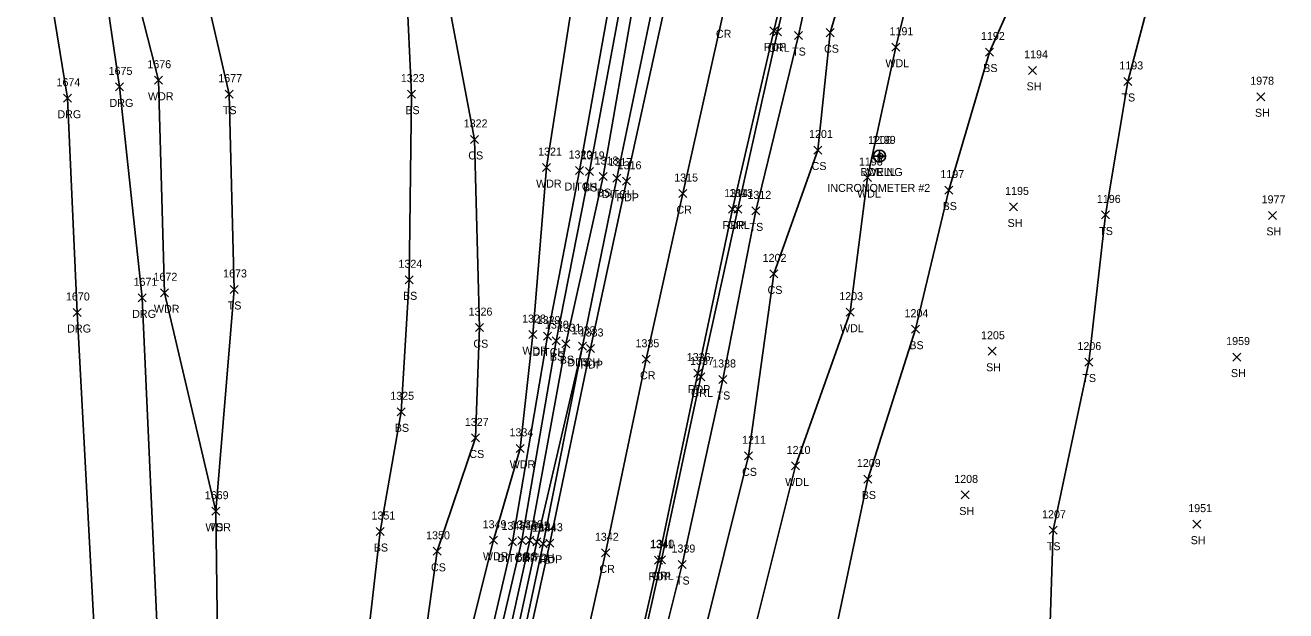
# Model space of a CAD drawing. Extents: x 1551995 to 1555700, y 777276 to 783130.
# Drawn here: x 1554731.6 to 1555046.7, y 777809.8 to 777956 of the extents above; entities that cross this region are included whole.
import ezdxf

# ---------------------------------------------------------------- set-up
doc = ezdxf.new("R2010")
doc.units = 0
for name, color, linetype in [('D_A', 7, 'Continuous'), ('D_I', 7, 'Continuous'), ('D_TIC', 7, 'Continuous'), ('DD', 7, 'Continuous'), ('G_A', 7, 'Continuous'), ('G_I', 7, 'Continuous'), ('GA_P', 7, 'Continuous'), ('L_A', 7, 'Continuous'), ('L_I', 7, 'Continuous'), ('L_TIC', 7, 'Continuous'), ('LAWA', 7, 'Continuous'), ('LELB', 7, 'Continuous'), ('P_A', 7, 'Continuous'), ('P_I', 7, 'Continuous'), ('P_TIC', 7, 'Continuous'), ('PET', 7, 'Continuous'), ('PRC', 7, 'Continuous'), ('R_A', 7, 'Continuous'), ('R_I', 7, 'Continuous'), ('R_TIC', 7, 'Continuous'), ('RDG', 7, 'Continuous'), ('RGR', 7, 'Continuous'), ('U_A', 7, 'Continuous'), ('U_C', 7, 'Continuous'), ('U_I', 7, 'Continuous'), ('UWW', 7, 'Continuous')]:
    doc.layers.add(name, color=color, linetype=linetype)

msp = doc.modelspace()

# ---------------------------------------------------------------- linework, layer by layer
at = {"layer": 'D_TIC'}
for points in [[(1554869.22, 777918.72), (1554871.22, 777920.72)], [(1554871.22, 777918.72), (1554869.22, 777920.72)], [(1554878.52, 777916.82), (1554880.52, 777918.82)], [(1554880.52, 777916.82), (1554878.52, 777918.82)], [(1554861.18, 777877.39), (1554863.18, 777879.39)], [(1554863.18, 777877.39), (1554861.18, 777879.39)], [(1554869.92, 777874.83), (1554871.92, 777876.83)], [(1554871.92, 777874.83), (1554869.92, 777876.83)], [(1554852.39, 777825.98), (1554854.39, 777827.98)], [(1554854.39, 777825.98), (1554852.39, 777827.98)], [(1554858.53, 777826.03), (1554860.53, 777828.03)], [(1554860.53, 777826.03), (1554858.53, 777828.03)]]:
    msp.add_lwpolyline(points, dxfattribs=at)
at = {"layer": 'DD'}
for points in [[(1554922.06, 778109.96), (1554923.19, 778109.15), (1554925.69, 778108.05), (1554928.67, 778106.77), (1554922.03, 778089.94), (1554922.01, 778087.44), (1554918.96, 778075.67), (1554907.32, 778037.79), (1554897.01, 777996.11), (1554888.71, 777961.75), (1554879.52, 777917.82), (1554870.92, 777875.83), (1554859.53, 777827.03), (1554848.28, 777775.3), (1554842.42, 777742.65), (1554832.08, 777696.16), (1554826.68, 777674.46), (1554825.9, 777662.94)], [(1554922.06, 778109.96), (1554914.41, 778091.96), (1554910.4, 778079.82), (1554897.71, 778040.99), (1554886.57, 777998.5), (1554878.33, 777965.3), (1554870.22, 777919.72), (1554862.18, 777878.39), (1554853.39, 777826.98), (1554841.81, 777777.5)]]:
    msp.add_lwpolyline(points, dxfattribs=at)
at = {"layer": 'GA_P'}
for p, q in [((1554945.18, 777923.34), (1554945.18, 777924.84)), ((1554945.18, 777923.34), (1554943.68, 777923.34)), ((1554946.68, 777923.34), (1554945.18, 777923.34)), ((1554945.18, 777921.84), (1554945.18, 777923.34))]:
    msp.add_line(p, q, dxfattribs=at)
for start, end in [(90, 180), (0, 90), (180, 270), (270, 0)]:
    msp.add_arc((1554945.18, 777923.34), 1.5, start, end, dxfattribs=at)
at = {"layer": 'L_TIC'}
for points in [[(1554923.92, 777952.42), (1554925.92, 777954.42)], [(1554925.92, 777952.42), (1554923.92, 777954.42)], [(1554931.87, 777953.14), (1554933.87, 777955.14)], [(1554933.87, 777953.14), (1554931.87, 777955.14)], [(1554948.24, 777949.5), (1554950.24, 777951.5)], [(1554950.24, 777949.5), (1554948.24, 777951.5)], [(1554971.66, 777948.31), (1554973.66, 777950.31)], [(1554973.66, 777948.31), (1554971.66, 777950.31)], [(1554763.95, 777941.26), (1554765.95, 777943.26)], [(1554765.95, 777941.26), (1554763.95, 777943.26)], [(1554982.45, 777943.73), (1554984.45, 777945.73)], [(1554984.45, 777943.73), (1554982.45, 777945.73)], [(1555006.25, 777940.96), (1555008.25, 777942.96)], [(1555008.25, 777940.96), (1555006.25, 777942.96)], [(1554781.62, 777937.78), (1554783.62, 777939.78)], [(1554783.62, 777937.78), (1554781.62, 777939.78)], [(1554827.21, 777937.79), (1554829.21, 777939.79)], [(1554829.21, 777937.79), (1554827.21, 777939.79)], [(1555039.54, 777937.14), (1555041.54, 777939.14)], [(1555041.54, 777937.14), (1555039.54, 777939.14)], [(1554842.93, 777926.48), (1554844.93, 777928.48)], [(1554844.93, 777926.48), (1554842.93, 777928.48)], [(1554928.76, 777923.84), (1554930.76, 777925.84)], [(1554930.76, 777923.84), (1554928.76, 777925.84)], [(1554860.96, 777919.45), (1554862.96, 777921.45)], [(1554862.96, 777919.45), (1554860.96, 777921.45)], [(1554871.66, 777918.49), (1554873.66, 777920.49)], [(1554873.66, 777918.49), (1554871.66, 777920.49)], [(1554875.08, 777917.21), (1554877.08, 777919.21)], [(1554877.08, 777917.21), (1554875.08, 777919.21)], [(1554941.15, 777916.97), (1554943.15, 777918.97)], [(1554943.15, 777916.97), (1554941.15, 777918.97)], [(1554961.52, 777913.84), (1554963.52, 777915.84)], [(1554963.52, 777913.84), (1554961.52, 777915.84)], [(1554977.71, 777909.63), (1554979.71, 777911.63)], [(1554979.71, 777909.63), (1554977.71, 777911.63)], [(1554913.28, 777908.64), (1554915.28, 777910.64)], [(1554915.28, 777908.64), (1554913.28, 777910.64)], [(1555000.69, 777907.63), (1555002.69, 777909.63)], [(1555002.69, 777907.63), (1555000.69, 777909.63)], [(1555042.39, 777907.52), (1555044.39, 777909.52)], [(1555044.39, 777907.52), (1555042.39, 777909.52)], [(1554826.61, 777891.43), (1554828.61, 777893.43)], [(1554828.61, 777891.43), (1554826.61, 777893.43)], [(1554917.75, 777892.91), (1554919.75, 777894.91)], [(1554919.75, 777892.91), (1554917.75, 777894.91)], [(1554765.43, 777888.19), (1554767.43, 777890.19)], [(1554767.43, 777888.19), (1554765.43, 777890.19)], [(1554782.83, 777889.02), (1554784.83, 777891.02)], [(1554784.83, 777889.02), (1554782.83, 777891.02)], [(1554936.88, 777883.35), (1554938.88, 777885.35)], [(1554938.88, 777883.35), (1554936.88, 777885.35)], [(1554844.21, 777879.49), (1554846.21, 777881.49)], [(1554846.21, 777879.49), (1554844.21, 777881.49)], [(1554953.2, 777879.1), (1554955.2, 777881.1)], [(1554955.2, 777879.1), (1554953.2, 777881.1)], [(1554857.53, 777877.75), (1554859.53, 777879.75)], [(1554859.53, 777877.75), (1554857.53, 777879.75)], [(1554863.33, 777876.23), (1554865.33, 777878.23)], [(1554865.33, 777876.23), (1554863.33, 777878.23)], [(1554865.8, 777875.47), (1554867.8, 777877.47)], [(1554867.8, 777875.47), (1554865.8, 777877.47)], [(1554869.92, 777874.83), (1554871.92, 777876.83)], [(1554871.92, 777874.83), (1554869.92, 777876.83)], [(1554972.33, 777873.59), (1554974.33, 777875.59)], [(1554974.33, 777873.59), (1554972.33, 777875.59)], [(1555033.54, 777872.14), (1555035.54, 777874.14)], [(1555035.54, 777872.14), (1555033.54, 777874.14)], [(1554996.48, 777870.9), (1554998.48, 777872.9)], [(1554998.48, 777870.9), (1554996.48, 777872.9)], [(1554905.04, 777866.54), (1554907.04, 777868.54)], [(1554907.04, 777866.54), (1554905.04, 777868.54)], [(1554824.56, 777858.47), (1554826.56, 777860.47)], [(1554826.56, 777858.47), (1554824.56, 777860.47)], [(1554843.2, 777851.94), (1554845.2, 777853.94)], [(1554845.2, 777851.94), (1554843.2, 777853.94)], [(1554854.37, 777849.35), (1554856.37, 777851.35)], [(1554856.37, 777849.35), (1554854.37, 777851.35)], [(1554911.39, 777847.48), (1554913.39, 777849.48)], [(1554913.39, 777847.48), (1554911.39, 777849.48)], [(1554923.17, 777844.95), (1554925.17, 777846.95)], [(1554925.17, 777844.95), (1554923.17, 777846.95)], [(1554941.29, 777841.69), (1554943.29, 777843.69)], [(1554943.29, 777841.69), (1554941.29, 777843.69)], [(1554965.63, 777837.71), (1554967.63, 777839.71)], [(1554967.63, 777837.71), (1554965.63, 777839.71)], [(1554778.3, 777833.65), (1554780.3, 777835.65)], [(1554780.3, 777833.65), (1554778.3, 777835.65)], [(1554778.3, 777833.65), (1554780.3, 777835.65)], [(1554780.3, 777833.65), (1554778.3, 777835.65)], [(1554819.31, 777828.58), (1554821.31, 777830.58)], [(1554821.31, 777828.58), (1554819.31, 777830.58)], [(1554987.59, 777828.9), (1554989.59, 777830.9)], [(1554989.59, 777828.9), (1554987.59, 777830.9)], [(1555023.47, 777830.42), (1555025.47, 777832.42)], [(1555025.47, 777830.42), (1555023.47, 777832.42)], [(1554847.67, 777826.4), (1554849.67, 777828.4)], [(1554849.67, 777826.4), (1554847.67, 777828.4)], [(1554854.73, 777826.33), (1554856.73, 777828.33)], [(1554856.73, 777826.33), (1554854.73, 777828.33)], [(1554856.76, 777826.38), (1554858.76, 777828.38)], [(1554858.76, 777826.38), (1554856.76, 777828.38)], [(1554860.08, 777825.54), (1554862.08, 777827.54)], [(1554862.08, 777825.54), (1554860.08, 777827.54)], [(1554833.62, 777823.64), (1554835.62, 777825.64)], [(1554835.62, 777823.64), (1554833.62, 777825.64)], [(1554894.88, 777820.34), (1554896.88, 777822.34)], [(1554896.88, 777820.34), (1554894.88, 777822.34)]]:
    msp.add_lwpolyline(points, dxfattribs=at)
at = {"layer": 'LAWA'}
for points in [[(1555000.96, 778294.87), (1554977.33, 778249.83), (1554953.65, 778203.43), (1554934.13, 778158.37), (1554921.74, 778129.69), (1554915, 778109.12), (1554905.48, 778082.18), (1554899.62, 778064.01), (1554889.87, 778042.09), (1554882.71, 778000.01), (1554871.69, 777971.47), (1554868.37, 777961.54), (1554861.96, 777920.45), (1554858.53, 777878.75), (1554855.37, 777850.35), (1554848.67, 777827.4), (1554836.72, 777779.63)], [(1555085.12, 778246.6), (1555062.11, 778217.51), (1555036.75, 778197.89), (1555030.02, 778178.79), (1555023.09, 778154.13), (1555005.22, 778133.85), (1555000.72, 778121.06), (1554983.85, 778091.44), (1554975.19, 778092.03), (1554970.99, 778074.93), (1554967.22, 778059.88), (1554967.17, 778023.98), (1554956.28, 777979.25), (1554949.24, 777950.5), (1554942.15, 777917.97), (1554937.88, 777884.35), (1554924.17, 777845.95), (1554911.99, 777797.39)], [(1554753.38, 777699.82), (1554782.17, 777718.85), (1554781.09, 777755.32), (1554779.76, 777796.52), (1554779.3, 777834.65), (1554766.43, 777889.19), (1554764.95, 777942.26), (1554753, 777988.87), (1554759.44, 778026.67), (1554773.64, 778068.32), (1554781.91, 778071.15), (1554798.07, 778075.08), (1554813.64, 778080.72)]]:
    msp.add_lwpolyline(points, dxfattribs=at)
at = {"layer": 'LELB'}
for points in [[(1555012.41, 778287.51), (1554987.42, 778242.35), (1554964.94, 778198.34), (1554949.46, 778165.73), (1554942.04, 778145.43), (1554936.48, 778136), (1554931.2, 778126.36), (1554925.41, 778115.96), (1554925.69, 778108.05), (1554919.03, 778090.31), (1554918.44, 778089.95), (1554914.24, 778077.2), (1554901.57, 778039.07), (1554894.39, 777997.12), (1554883.88, 777962.74), (1554876.08, 777918.21), (1554866.8, 777876.47), (1554857.76, 777827.38), (1554846.36, 777775.83)], [(1554779.3, 777834.65), (1554783.83, 777890.02), (1554782.62, 777938.78), (1554771.14, 777988.74), (1554776.92, 778021.99), (1554786.75, 778049.64), (1554798.07, 778075.08), (1554788.09, 778101.73), (1554789.42, 778116.55), (1554786.7, 778124.19), (1554777.52, 778125.41), (1554776.84, 778134.51)], [(1554925.41, 778115.96), (1554923.19, 778109.15), (1554916.16, 778091.42), (1554916.06, 778090.22), (1554912.35, 778078.2), (1554899.83, 778040.36), (1554892.76, 777999.54), (1554881.05, 777964.27), (1554872.66, 777919.49), (1554864.33, 777877.23), (1554855.73, 777827.33), (1554843.83, 777776.52)], [(1554956.78, 778082.85), (1554952.54, 778067.25), (1554941.7, 778025.45), (1554932.23, 777987.42), (1554924.92, 777953.42), (1554914.28, 777909.64), (1554906.04, 777867.54), (1554895.88, 777821.34), (1554882.23, 777767.05), (1554874.85, 777730.37), (1554865.16, 777689.06), (1554854.06, 777643.96), (1554841.07, 777598.56), (1554825.8, 777560.58)], [(1554954.84, 778026.93), (1554940.94, 777981.64), (1554932.87, 777954.14), (1554929.76, 777924.84), (1554918.75, 777893.91), (1554912.39, 777848.48), (1554900.26, 777799.7), (1554891.71, 777757.62), (1554881.43, 777720.27), (1554874.58, 777680.06), (1554873.83, 777672.65), (1554864.12, 777644.24), (1554854.56, 777607.14), (1554832.26, 777556.58)], [(1555000.87, 778001.08), (1555009.49, 778000.82), (1555019.32, 777999.5), (1555016.45, 777976.79), (1555007.25, 777941.96), (1555001.69, 777908.63), (1554997.48, 777871.9), (1554988.59, 777829.9), (1554987.68, 777801.59), (1554990.67, 777771.72), (1554987.39, 777735.48), (1554982.18, 777719.34), (1554965.91, 777692.12), (1554960.8, 777672.01)], [(1554989.73, 777998.18), (1554984.34, 777975.58), (1554972.66, 777949.31), (1554962.52, 777914.84), (1554954.2, 777880.1), (1554942.29, 777842.69), (1554932.5, 777796.7), (1554925.54, 777781.17), (1554929.46, 777763.36)], [(1554818.74, 777989.99), (1554826.95, 777965.67), (1554828.21, 777938.79), (1554827.61, 777892.43), (1554825.56, 777859.47), (1554820.31, 777829.58), (1554817.04, 777800.55), (1554813.37, 777784.98), (1554810.59, 777751.68), (1554805.09, 777735), (1554803.57, 777724.87), (1554801.62, 777701.82), (1554799.08, 777679.52), (1554798, 777658.89), (1554794.95, 777639.81), (1554778.13, 777607.5), (1554759.36, 777559.57), (1554752.31, 777545.79)], [(1554828.62, 777989.99), (1554839.45, 777979.91), (1554836.31, 777967.58), (1554843.93, 777927.48), (1554845.21, 777880.49), (1554844.2, 777852.94), (1554834.62, 777824.64), (1554828.42, 777780.47), (1554821.65, 777751.51), (1554810.59, 777751.68)], [(1554870.92, 777875.83), (1554861.08, 777826.54), (1554850.05, 777774.56), (1554843.76, 777742.91), (1554832.54, 777696.52), (1554826.68, 777674.46)]]:
    msp.add_lwpolyline(points, dxfattribs=at)
at = {"layer": 'P_TIC'}
for points in [[(1554917.72, 777953.59), (1554919.72, 777955.59)], [(1554919.72, 777953.59), (1554917.72, 777955.59)], [(1554880.9, 777916.03), (1554882.9, 777918.03)], [(1554882.9, 777916.03), (1554880.9, 777918.03)], [(1554894.98, 777912.96), (1554896.98, 777914.96)], [(1554896.98, 777912.96), (1554894.98, 777914.96)], [(1554907.46, 777909.08), (1554909.46, 777911.08)], [(1554909.46, 777909.08), (1554907.46, 777911.08)], [(1554871.92, 777874.28), (1554873.92, 777876.28)], [(1554873.92, 777874.28), (1554871.92, 777876.28)], [(1554885.88, 777871.59), (1554887.88, 777873.59)], [(1554887.88, 777871.59), (1554885.88, 777873.59)], [(1554898.75, 777868.14), (1554900.75, 777870.14)], [(1554900.75, 777868.14), (1554898.75, 777870.14)], [(1554861.74, 777825.66), (1554863.74, 777827.66)], [(1554863.74, 777825.66), (1554861.74, 777827.66)], [(1554875.72, 777823.26), (1554877.72, 777825.26)], [(1554877.72, 777823.26), (1554875.72, 777825.26)], [(1554888.9, 777821.39), (1554890.9, 777823.39)], [(1554890.9, 777821.39), (1554888.9, 777823.39)]]:
    msp.add_lwpolyline(points, dxfattribs=at)
at = {"layer": 'PET'}
for points in [[(1555086.85, 778385.99), (1555058.53, 778347.95), (1555034.13, 778312.76), (1555016.69, 778284.76), (1554990.68, 778240.38), (1554968.05, 778196.33), (1554953.03, 778164.25), (1554940.37, 778132.83), (1554930.99, 778106.02), (1554923.77, 778083.63), (1554909.85, 778036.75), (1554900.04, 777995.37), (1554891.67, 777961.45), (1554881.9, 777917.03), (1554872.92, 777875.28), (1554862.74, 777826.66), (1554851.19, 777774.32)], [(1555108.52, 778369.81), (1555078.86, 778330.23), (1555056.92, 778298.28), (1555038.33, 778268.72), (1555013, 778223.52), (1554996, 778190.4), (1554978.91, 778154.53), (1554967.24, 778125.11), (1554957.25, 778096.67), (1554950.17, 778073.38), (1554937.06, 778028.22), (1554926.8, 777988.52), (1554918.72, 777954.59), (1554908.46, 777910.08), (1554899.75, 777869.14), (1554889.9, 777822.39), (1554877.4, 777767.74)]]:
    msp.add_lwpolyline(points, dxfattribs=at)
at = {"layer": 'PRC'}
msp.add_lwpolyline([(1555098.33, 778377.48), (1555069.71, 778339.49), (1555045.49, 778304.7), (1555028.73, 778278.05), (1555002.89, 778234.08), (1554980, 778189.5), (1554966.22, 778159.18), (1554954.38, 778129.46), (1554944.07, 778101.03), (1554941.59, 778092.54), (1554937.34, 778078.77), (1554924.27, 778032.77), (1554914.16, 777991.62), (1554905.84, 777957.86), (1554895.98, 777913.96), (1554886.88, 777872.59), (1554876.72, 777824.26), (1554864.6, 777770.35)], dxfattribs=at)
at = {"layer": 'R_TIC'}
for points in [[(1554918.66, 777953.37), (1554920.66, 777955.37)], [(1554920.66, 777953.37), (1554918.66, 777955.37)], [(1554754.21, 777939.6), (1554756.21, 777941.6)], [(1554756.21, 777939.6), (1554754.21, 777941.6)], [(1554741.18, 777936.77), (1554743.18, 777938.77)], [(1554743.18, 777936.77), (1554741.18, 777938.77)], [(1554908.72, 777909.11), (1554910.72, 777911.11)], [(1554910.72, 777909.11), (1554908.72, 777911.11)], [(1554759.87, 777886.93), (1554761.87, 777888.93)], [(1554761.87, 777886.93), (1554759.87, 777888.93)], [(1554743.63, 777883.27), (1554745.63, 777885.27)], [(1554745.63, 777883.27), (1554743.63, 777885.27)], [(1554899.5, 777867.18), (1554901.5, 777869.18)], [(1554901.5, 777867.18), (1554899.5, 777869.18)], [(1554889.69, 777821.54), (1554891.69, 777823.54)], [(1554891.69, 777821.54), (1554889.69, 777823.54)]]:
    msp.add_lwpolyline(points, dxfattribs=at)
at = {"layer": 'RDG'}
for points in [[(1554731.76, 777736.57), (1554744.54, 777760.39), (1554749.58, 777791.25), (1554744.63, 777884.27), (1554742.18, 777937.77), (1554733.78, 777989.36), (1554731.62, 778029.74), (1554732.87, 778072.64), (1554738.87, 778112.72), (1554741.1, 778122.89), (1554752.14, 778165.58), (1554757.04, 778182.47), (1554765.14, 778213.69), (1554774.89, 778246.18), (1554785.77, 778269.3), (1554800.7, 778290.2), (1554833.81, 778326.22), (1554863.94, 778353.44), (1554894.55, 778381.82), (1554916.32, 778408.8)], [(1554765.41, 777786.83), (1554760.87, 777887.93), (1554755.21, 777940.6), (1554748.12, 777988.97), (1554746.63, 778028.6), (1554748.07, 778068.94), (1554755.05, 778099.35), (1554759.31, 778115.55), (1554764.29, 778135.87), (1554767.84, 778151.77), (1554770.94, 778162.89), (1554771.35, 778163.02), (1554773.41, 778171.97), (1554775.55, 778183.39), (1554780.94, 778209.88), (1554780.41, 778210.35), (1554788.23, 778232), (1554795.94, 778253.78), (1554801.81, 778267.78), (1554821.53, 778293.59), (1554841.19, 778314.82), (1554873.15, 778342.35), (1554907.49, 778367.57), (1554931.47, 778399.39)]]:
    msp.add_lwpolyline(points, dxfattribs=at)
at = {"layer": 'RGR'}
msp.add_lwpolyline([(1555039.56, 778268.3), (1555013.62, 778223), (1554996.63, 778189.88), (1554979.88, 778154.08), (1554968.24, 778124.65), (1554958.2, 778096.32), (1554950.97, 778072.94), (1554937.27, 778027.95), (1554927.65, 777988.1), (1554919.66, 777954.37), (1554909.72, 777910.11), (1554900.5, 777868.18), (1554890.69, 777822.54), (1554878.36, 777767.59), (1554870.52, 777731.32), (1554860.9, 777689.38), (1554849.55, 777645.14), (1554835.81, 777600.33), (1554822.79, 777564.15), (1554817.07, 777548.72), (1554816.7, 777536.06)], dxfattribs=at)
at = {"layer": 'UWW'}
for radius in [0.625, 0.0833]:
    msp.add_circle((1554945.4, 777923.37), radius, dxfattribs=at)

# ---------------------------------------------------------------- texts
at = {"layer": 'D_A'}
for p in [(1554866.45, 777914.72), (1554875.76, 777912.82), (1554858.42, 777873.39), (1554867.15, 777870.83), (1554849.63, 777821.98), (1554855.76, 777822.03)]:
    msp.add_text('DITCH', height=2, dxfattribs=at).set_placement(p)
at = {"layer": 'D_I'}
for s, p in [('1320', (1554867.44, 777922.72)), ('1317', (1554877.4, 777920.82)), ('1329', (1554859.48, 777881.39)), ('1332', (1554868.22, 777878.83)), ('1348', (1554850.7, 777829.98)), ('1345', (1554856.83, 777830.03))]:
    msp.add_text(s, height=2, dxfattribs=at).set_placement(p)
at = {"layer": 'G_A'}
msp.add_text('BORING', height=2, dxfattribs=at).set_placement((1554940.41, 777918.34))
at = {"layer": 'G_I'}
msp.add_text('1200', height=2, dxfattribs=at).set_placement((1554942.32, 777926.34))
at = {"layer": 'L_A'}
for s, p in [('TS', (1554923.33, 777948.42)), ('CS', (1554931.31, 777949.14)), ('WDL', (1554946.65, 777945.5)), ('BS', (1554971.11, 777944.31)), ('SH', (1554981.94, 777939.73)), ('WDR', (1554762.31, 777937.26)), ('TS', (1555005.66, 777936.96)), ('TS', (1554781.03, 777933.78)), ('BS', (1554826.65, 777933.79)), ('SH', (1555039.03, 777933.14)), ('CS', (1554842.37, 777922.48)), ('CS', (1554928.2, 777919.84)), ('WDR', (1554859.33, 777915.45)), ('BS', (1554871.1, 777914.49)), ('BS', (1554874.52, 777913.21)), ('WDL', (1554939.57, 777912.97)), ('BS', (1554960.96, 777909.84)), ('TS', (1554912.69, 777904.64)), ('SH', (1554977.19, 777905.63)), ('TS', (1555000.1, 777903.63)), ('SH', (1555041.88, 777903.52)), ('CS', (1554917.19, 777888.91)), ('TS', (1554782.24, 777885.02)), ('BS', (1554826.05, 777887.43)), ('WDR', (1554763.79, 777884.19)), ('WDL', (1554935.3, 777879.35)), ('CS', (1554843.65, 777875.49)), ('BS', (1554952.64, 777875.1)), ('WDR', (1554855.89, 777873.75)), ('BS', (1554862.77, 777872.23)), ('BS', (1554865.24, 777871.47)), ('TS', (1554869.33, 777870.83)), ('SH', (1554971.82, 777869.59)), ('TS', (1554995.89, 777866.9)), ('SH', (1555033.03, 777868.14)), ('TS', (1554904.45, 777862.54)), ('BS', (1554824, 777854.47)), ('CS', (1554842.64, 777847.94)), ('WDR', (1554852.74, 777845.35)), ('CS', (1554910.83, 777843.48)), ('WDL', (1554921.59, 777840.95)), ('BS', (1554940.73, 777837.69)), ('SH', (1554965.12, 777833.71)), ('WDR', (1554776.67, 777829.65)), ('TS', (1554777.71, 777829.65)), ('BS', (1554818.75, 777824.58)), ('TS', (1554987, 777824.9)), ('SH', (1555022.96, 777826.42)), ('WDR', (1554846.03, 777822.4)), ('BS', (1554854.17, 777822.33)), ('BS', (1554856.2, 777822.38)), ('TS', (1554859.49, 777821.54)), ('CS', (1554833.06, 777819.64)), ('TS', (1554894.29, 777816.34))]:
    msp.add_text(s, height=2, dxfattribs=at).set_placement(p)
at = {"layer": 'L_I'}
for s, p in [('1191', (1554947.68, 777953.5)), ('1192', (1554970.54, 777952.31)), ('1194', (1554981.33, 777947.73)), ('1676', (1554762.15, 777945.26)), ('1193', (1555005.13, 777944.96)), ('1677', (1554779.88, 777941.78)), ('1323', (1554825.51, 777941.79)), ('1978', (1555037.85, 777941.14)), ('1322', (1554841.23, 777930.48)), ('1201', (1554927.56, 777927.84)), ('1321', (1554859.84, 777923.45)), ('1319', (1554870.52, 777922.49)), ('1318', (1554873.96, 777921.21)), ('1198', (1554940.02, 777920.97)), ('1197', (1554960.39, 777917.84)), ('1195', (1554976.58, 777913.63)), ('1312', (1554912.16, 777912.64)), ('1196', (1554999.51, 777911.63)), ('1977', (1555040.7, 777911.52)), ('1202', (1554915.97, 777896.91)), ('1324', (1554824.92, 777895.43)), ('1672', (1554763.69, 777892.19)), ('1673', (1554781.09, 777893.02)), ('1203', (1554935.11, 777887.35)), ('1326', (1554842.46, 777883.49)), ('1328', (1554855.83, 777881.75)), ('1204', (1554951.43, 777883.1)), ('1330', (1554861.55, 777880.23)), ('1331', (1554864.67, 777879.47)), ('1332', (1554868.22, 777878.83)), ('1205', (1554970.56, 777877.59)), ('1206', (1554994.65, 777874.9)), ('1959', (1555031.84, 777876.14)), ('1338', (1554903.35, 777870.54)), ('1325', (1554822.87, 777862.47)), ('1327', (1554841.51, 777855.94)), ('1334', (1554852.68, 777853.35)), ('1211', (1554910.83, 777851.48)), ('1210', (1554921.96, 777848.95)), ('1209', (1554939.51, 777845.69)), ('1208', (1554963.86, 777841.71)), ('1669', (1554776.51, 777837.65)), ('1669', (1554776.51, 777837.65)), ('1951', (1555022.35, 777834.42)), ('1351', (1554818.18, 777832.58)), ('1207', (1554985.82, 777832.9)), ('1350', (1554831.84, 777827.64)), ('1349', (1554845.97, 777830.4)), ('1347', (1554853.04, 777830.33)), ('1346', (1554855.02, 777830.38)), ('1344', (1554858.38, 777829.54)), ('1339', (1554893.18, 777824.34))]:
    msp.add_text(s, height=2, dxfattribs=at).set_placement(p)
at = {"layer": 'P_A'}
for s, p in [('CR', (1554904.28, 777952.86)), ('RDP', (1554916.21, 777949.59)), ('RDP', (1554879.39, 777912.03)), ('CR', (1554894.42, 777908.96)), ('RDP', (1554905.95, 777905.08)), ('RDP', (1554870.41, 777870.28)), ('CR', (1554885.31, 777867.59)), ('RDP', (1554897.24, 777864.14)), ('RDP', (1554860.23, 777821.66)), ('CR', (1554875.15, 777819.26)), ('RDP', (1554887.39, 777817.39))]:
    msp.add_text(s, height=2, dxfattribs=at).set_placement(p)
at = {"layer": 'P_I'}
for s, p in [('1316', (1554879.72, 777920.03)), ('1315', (1554893.86, 777916.96)), ('1314', (1554906.34, 777913.08)), ('1333', (1554870.23, 777878.28)), ('1335', (1554884.18, 777875.59)), ('1336', (1554897, 777872.14)), ('1343', (1554860.05, 777829.66)), ('1342', (1554874.03, 777827.26)), ('1341', (1554887.77, 777825.39))]:
    msp.add_text(s, height=2, dxfattribs=at).set_placement(p)
at = {"layer": 'R_A'}
for s, p in [('GRL', (1554917.2, 777949.37)), ('DRG', (1554752.7, 777935.6)), ('DRG', (1554739.67, 777932.77)), ('GRL', (1554907.26, 777905.11)), ('DRG', (1554758.36, 777882.93)), ('DRG', (1554742.12, 777879.27)), ('GRL', (1554898.04, 777863.18)), ('GRL', (1554888.24, 777817.54))]:
    msp.add_text(s, height=2, dxfattribs=at).set_placement(p)
at = {"layer": 'R_I'}
for s, p in [('1675', (1554752.47, 777943.6)), ('1674', (1554739.44, 777940.77)), ('1313', (1554907.59, 777913.11)), ('1671', (1554758.7, 777890.93)), ('1670', (1554741.8, 777887.27)), ('1337', (1554897.81, 777871.18)), ('1340', (1554887.91, 777825.54))]:
    msp.add_text(s, height=2, dxfattribs=at).set_placement(p)
at = {"layer": 'U_A'}
msp.add_text('WELL', height=2, dxfattribs=at).set_placement((1554941.97, 777918.37))
at = {"layer": 'U_C'}
msp.add_text('INCRONOMETER #2', height=2, dxfattribs=at).set_placement((1554932.14, 777914.37))
at = {"layer": 'U_I'}
msp.add_text('1199', height=2, dxfattribs=at).set_placement((1554943.27, 777926.37))

doc.saveas('drawing.dxf')
